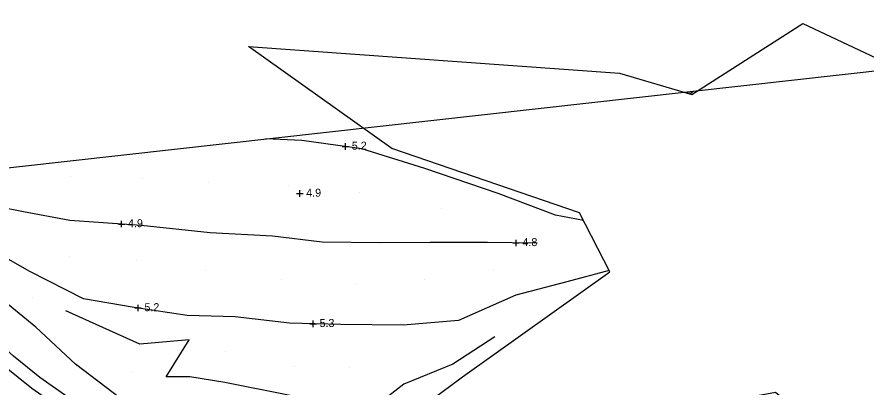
# Model space of a CAD drawing. Extents: x 2316231 to 2323598, y 363169 to 371906.
# Drawn here: x 2320088 to 2320618, y 371675 to 371906 of the extents above; entities that cross this region are included whole.
import ezdxf

# ---------------------------------------------------------------- set-up
doc = ezdxf.new("R2010")
doc.units = 0
for name, color, linetype in [('RD_DTM_BkLn1', 7, 'Continuous'), ('RD_DTM_Holes', 7, 'Continuous'), ('RD_DTM_Spot', 7, 'Continuous'), ('RD_DTM_TinHull', 7, 'Continuous'), ('RD_DTM_Void', 7, 'Continuous'), ('RD_EX_Road', 7, 'Continuous')]:
    doc.layers.add(name, color=color, linetype=linetype)

msp = doc.modelspace()

# ---------------------------------------------------------------- linework, layer by layer
at = {"layer": 'RD_DTM_BkLn1'}
for points in [[(2320504.818, 371858.732), (2320508.606, 371858.298), (2320510.048, 371859.5)], [(2320441.478, 371778.689), (2320424.071, 371782.168), (2320388.254, 371795.73), (2320342.318, 371811.341), (2320303.119, 371823.571), (2320265.601, 371828.705), (2320243.055, 371829.709)], [(2320247.447, 371589.255), (2320246.063, 371585.469), (2320237.332, 371599.813), (2320228.209, 371620.404), (2320213.705, 371630.209), (2320197.191, 371637.892), (2320178.161, 371648.205), (2320151.99, 371667.903), (2320124.207, 371689.163), (2320099.412, 371712.237), (2320073.669, 371733.087), (2320053.359, 371747.611), (2320033.617, 371763.252), (2320015.884, 371782.755), (2320020.033, 371799.84), (2320021.866, 371805.029)], [(2320412.588, 371764.546), (2320381.531, 371765.121), (2320345.73, 371764.979), (2320314.621, 371764.772), (2320278.299, 371765.158), (2320247.263, 371769.095), (2320208.313, 371771.121), (2320165.131, 371775.707), (2320120.492, 371778.868), (2320091.729, 371784.085), (2320061.85, 371789.928), (2320028.899, 371791.798)], [(2320457.491, 371747.59), (2320431.191, 371740.556), (2320399.329, 371732.229), (2320363.52, 371716.434), (2320328.821, 371713.402), (2320289.989, 371713.77), (2320257.918, 371714.69), (2320223.802, 371718.692), (2320193.949, 371719.562), (2320160.796, 371724.516), (2320129.197, 371729.786), (2320095.586, 371746.988), (2320059.474, 371767.286)], [(2320386.04, 371706.098), (2320359.934, 371688.992), (2320329.342, 371676.595), (2320302.219, 371655.678), (2320272.388, 371638.21), (2320258.291, 371669.468), (2320217.514, 371677.704), (2320195.604, 371681.254), (2320180.685, 371681.082), (2320195.134, 371704.264), (2320164.336, 371701.603), (2320118.036, 371722.283)]]:
    msp.add_lwpolyline(points, dxfattribs=at)
at = {"layer": 'RD_DTM_Holes'}
msp.add_lwpolyline([(2320578.515, 371901.805), (2320771.704, 371810.944), (2320759.467, 371792.3), (2320731.831, 371798.362), (2320674.729, 371681.294), (2320618.297, 371535.833), (2320573.974, 371578.83), (2320606.053, 371635.141), (2320561.406, 371671.405), (2320475.825, 371655.559), (2320351.275, 371609.908), (2320259.253, 371569.089), (2320245.733, 371592.183), (2320365.965, 371681.144), (2320457.914, 371746.768), (2320438.986, 371783.53), (2320321.808, 371823.754), (2320232.154, 371887.354), (2320464.075, 371870.831), (2320509.161, 371857.442), (2320578.515, 371901.805)], dxfattribs=at)
at = {"layer": 'RD_DTM_Spot'}
for p, q in [((2320121.299, 371806.188), (2320121.299, 371806.188)), ((2320166.102, 371804.918), (2320166.102, 371804.918)), ((2320207.443, 371802.537), (2320207.443, 371802.537)), ((2320257.458, 371800.416), (2320257.458, 371800.416)), ((2320301.518, 371796.186), (2320301.518, 371796.186)), ((2320352.744, 371786.376), (2320352.744, 371786.376)), ((2320449.784, 371762.03), (2320449.784, 371762.03)), ((2320120.379, 371756.06), (2320120.379, 371756.06)), ((2320162.329, 371753.909), (2320162.329, 371753.909)), ((2320205.569, 371747.49), (2320205.569, 371747.49)), ((2320385.354, 371748.066), (2320385.354, 371748.066)), ((2320252.539, 371742.027), (2320252.539, 371742.027)), ((2320342.454, 371742.099), (2320342.454, 371742.099)), ((2320299.841, 371739.036), (2320299.841, 371739.036)), ((2320097.338, 371730.81), (2320097.338, 371730.81)), ((2320218.117, 371696.913), (2320218.117, 371696.913)), ((2320159.463, 371684.488), (2320159.463, 371684.488)), ((2320260.768, 371687.813), (2320260.768, 371687.813)), ((2320295.395, 371686.993), (2320295.395, 371686.993))]:
    msp.add_line(p, q, dxfattribs=at)
at = {"layer": 'RD_DTM_TinHull'}
msp.add_lwpolyline([(2319782.271, 371232.132), (2319735.05, 371773.026), (2320925.274, 371905.831), (2321343.399, 371858.015), (2321109.741, 371125.092), (2321259.088, 370783.878), (2321451.866, 370308.131), (2321545.882, 369878.312), (2321496.483, 369600.925), (2321592.742, 369376.322), (2321772.553, 369180.585), (2321930.831, 369046.826), (2322410.389, 369187.058), (2322700.489, 369322.074), (2323031.423, 369488.086), (2323384.71, 369626.658), (2323598.112, 369182.404), (2323506.079, 369141.824), (2322749.057, 368805.183), (2322437.788, 368637.943)], dxfattribs=at)
at = {"layer": 'RD_DTM_Void'}
for p, q in [((2320292.753, 371822.989), (2320292.753, 371826.989)), ((2320290.753, 371824.989), (2320294.753, 371824.989)), ((2320262.267, 371795.621), (2320266.267, 371795.621)), ((2320264.267, 371793.621), (2320264.267, 371797.621)), ((2320152.917, 371774.572), (2320152.917, 371778.572)), ((2320150.917, 371776.572), (2320154.917, 371776.572)), ((2320397.375, 371764.791), (2320401.375, 371764.791)), ((2320399.375, 371762.791), (2320399.375, 371766.791)), ((2320163.193, 371722.158), (2320163.193, 371726.158)), ((2320161.193, 371724.158), (2320165.193, 371724.158)), ((2320272.612, 371712.268), (2320272.612, 371716.268)), ((2320270.612, 371714.268), (2320274.612, 371714.268))]:
    msp.add_line(p, q, dxfattribs=at)
at = {"layer": 'RD_EX_Road'}
for points in [[(2320246.881, 371569.64), (2320230.251, 371583.863), (2320208.471, 371601.164), (2320187.323, 371614.749), (2320169.072, 371628.605), (2320152.559, 371641.762), (2320134.659, 371656.393), (2320119.376, 371668.451), (2320101.825, 371680.68), (2320085.322, 371693.988), (2320072.195, 371706.009), (2320054.894, 371720.551), (2320038.085, 371735.884), (2320021.738, 371749.103), (2320010.879, 371756.871), (2319996.857, 371764.407)], [(2320242.411, 371562.654), (2320224.974, 371577.275), (2320203.553, 371594.291), (2320182.483, 371607.826), (2320163.889, 371621.942), (2320147.259, 371635.193), (2320129.374, 371649.812), (2320114.345, 371661.669), (2320096.757, 371673.923), (2320079.817, 371687.585), (2320066.627, 371699.663), (2320049.332, 371714.2), (2320032.582, 371729.479), (2320016.625, 371742.383), (2320006.407, 371749.692), (2319992.861, 371756.972)]]:
    msp.add_lwpolyline(points, dxfattribs=at)

# ---------------------------------------------------------------- texts
at = {"layer": 'RD_DTM_Void'}
for s, p in [('5.2', (2320296.753, 371822.989)), ('4.9', (2320268.267, 371793.621)), ('4.9', (2320156.917, 371774.572)), ('4.8', (2320403.375, 371762.791)), ('5.2', (2320167.193, 371722.158)), ('5.3', (2320276.612, 371712.268))]:
    msp.add_text(s, height=5, dxfattribs=at).set_placement(p)

doc.saveas('drawing.dxf')
